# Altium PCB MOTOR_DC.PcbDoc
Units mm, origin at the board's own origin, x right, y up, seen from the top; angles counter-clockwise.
Board outline 21.59 x 21.08 mm, 2 copper layers (Top Layer, Bottom Layer); 7 components, 7 nets, 22 pads, 0 vias.
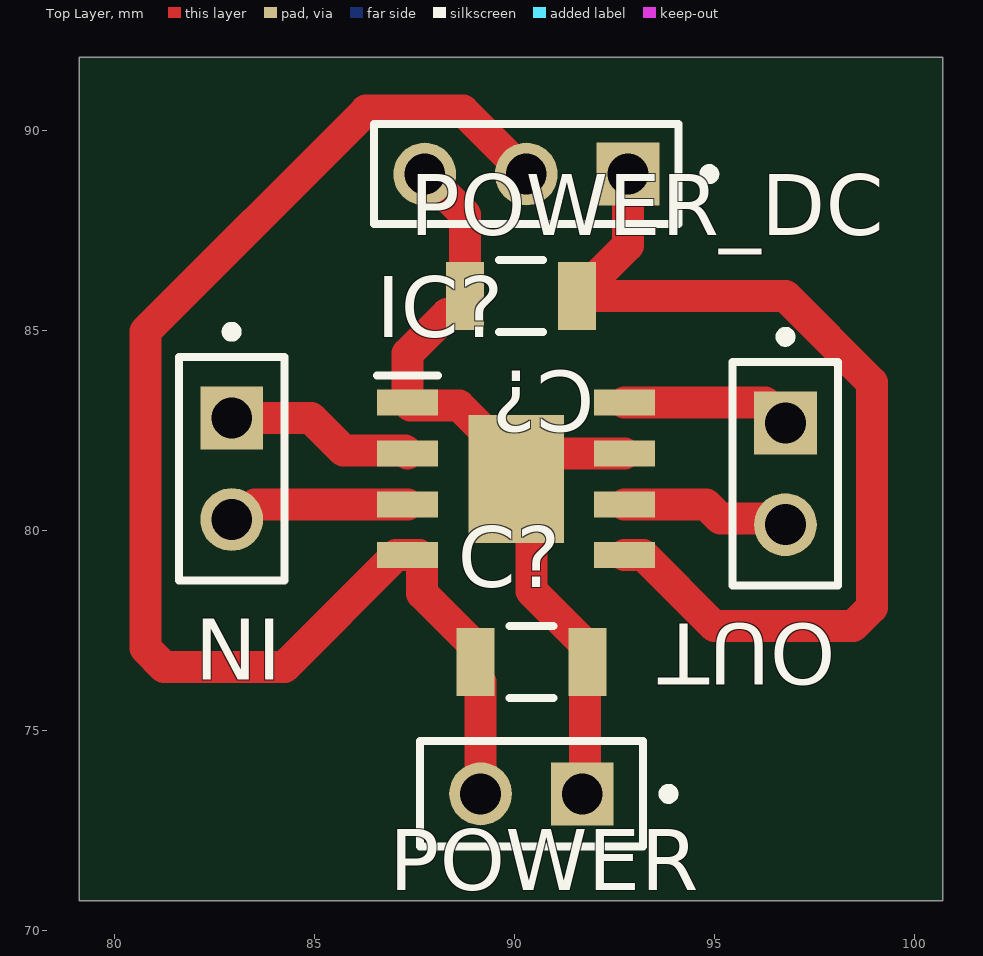
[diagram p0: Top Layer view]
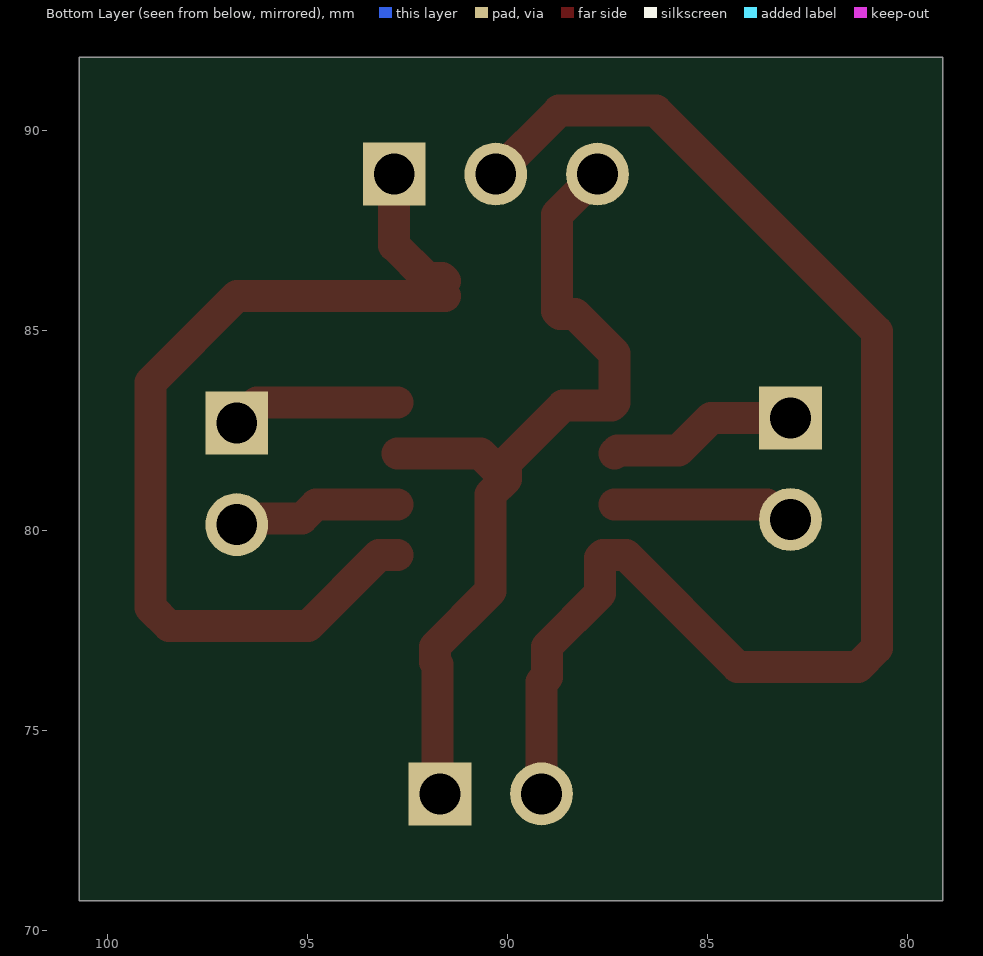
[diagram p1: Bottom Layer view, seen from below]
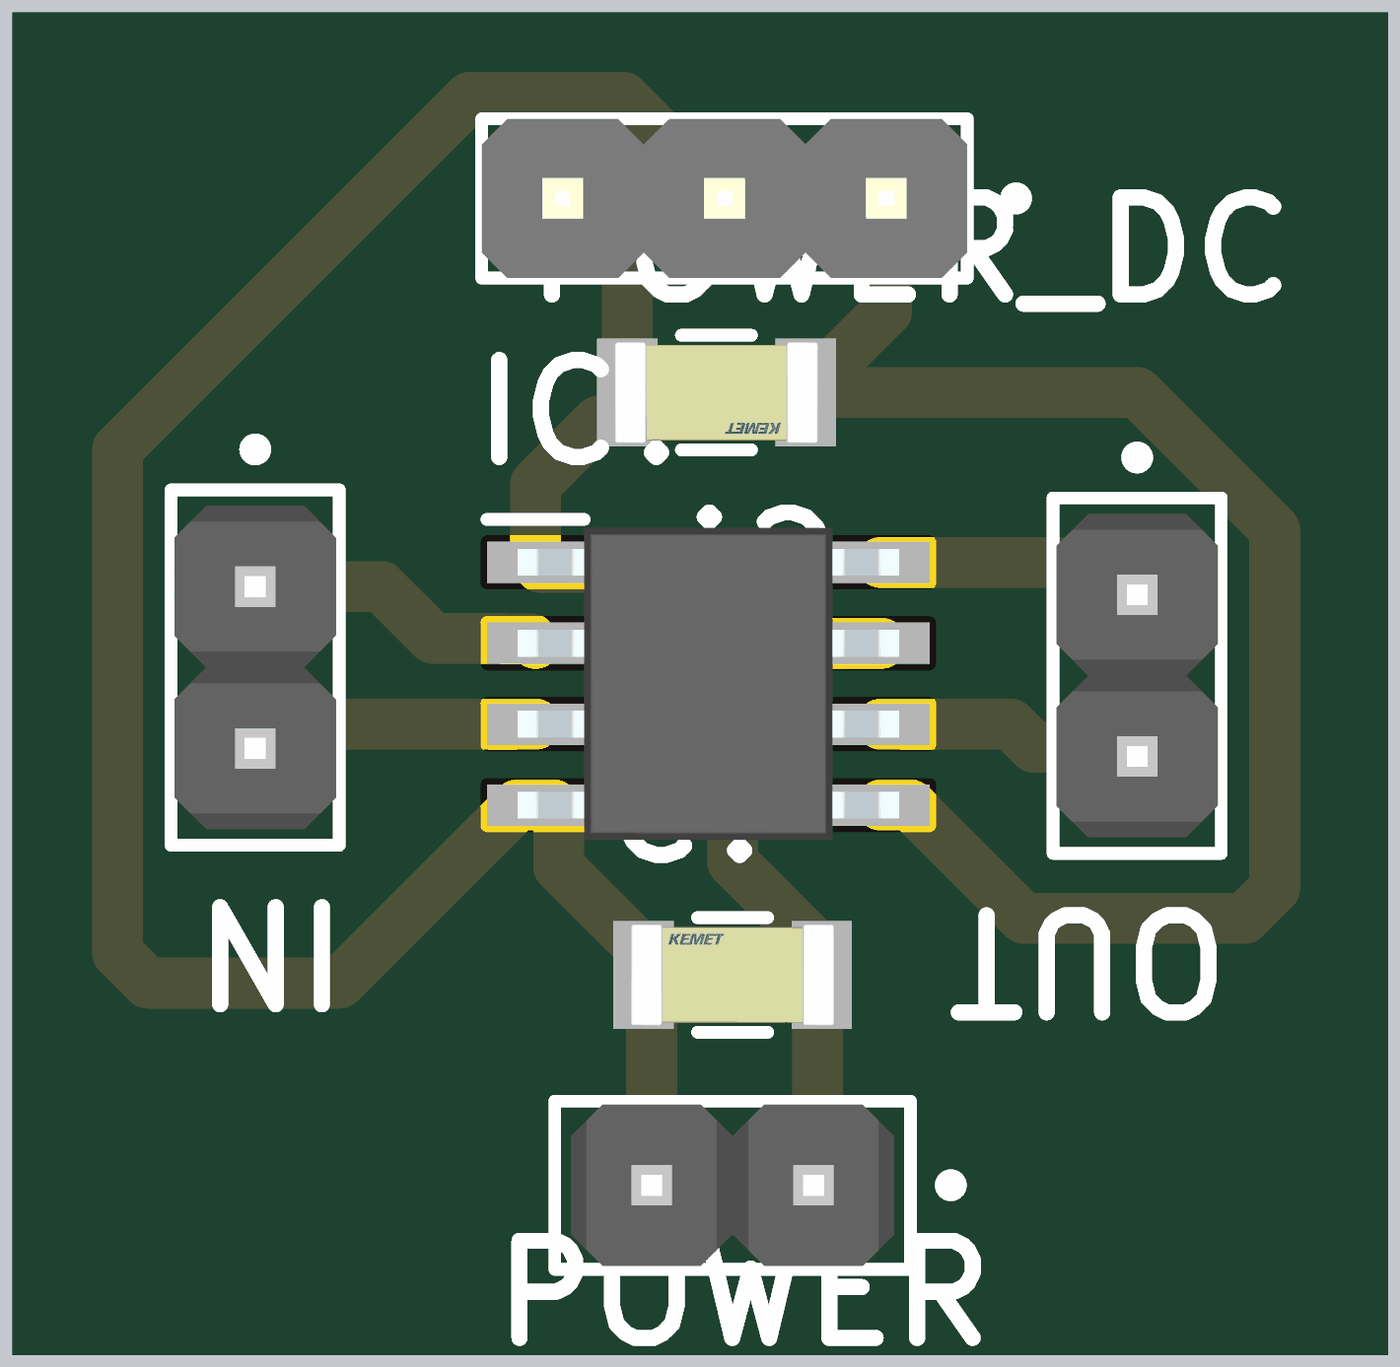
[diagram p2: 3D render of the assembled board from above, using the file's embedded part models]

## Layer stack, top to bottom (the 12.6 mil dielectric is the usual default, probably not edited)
Top Solder: solder mask 0.0102, Solder Resist, Dk 3.5
Top Layer: signal copper 0.0356
Dielectric 1: dielectric 0.32, FR-4, Dk 4.8
Bottom Layer: signal copper 0.0356
Bottom Solder: solder mask 0.0102, Solder Resist, Dk 3.5

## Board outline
79.121,70.739 79.121,91.821 100.711,91.821 100.711,70.739

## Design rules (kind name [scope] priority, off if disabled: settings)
Clearance [All] p1: gap=0.4 ignorepadtopadclearanceinfootprint=FALSE
PolygonConnect [All] p1: connectstyle=Relief reliefconductorwidth=0.254 reliefentries=4 polygonreliefangle="90 Angle" airgapwidth=0.254
RoutingVias [All] p1: holewidth=0.711 width=1.27 viastyle="Through Hole" minholewidth=0.711 minwidth=1.27 maxholewidth=0.711 maxwidth=1.27
SolderMaskExpansion [All] p1: expansion=0.102 istentingtop=FALSE
SupplyNets "Schematic Supply Nets" [InNet('GND')] p1: voltage=0.000
Width [All] p1: maxlimit=0.8 minlimit=0.254 preferedwidth=0.8 toplayer_minwidth=0.8 bottomlayer_maxwidth=0.254 bottomlayer_prefwidth=0.254 minimp=50.000000 maximp=50.000000 favimp=50.000000
30 further rules are at their usual default settings.

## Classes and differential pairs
component class MOTOR_DC: C? IC? IN OUT POWER

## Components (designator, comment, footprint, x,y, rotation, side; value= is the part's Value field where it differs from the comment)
C? "." FP-C1206C-EB-MFG 90.424,76.708 r0 top value="100 pF"
C? "." FP-C1206C-EB-MFG 90.17,85.852 r180 top value="100 pF"
IC? "TB67H451FNG" SOIC127P600X170-9N 90.043,81.28 r0 top
IN "M20-9990246" FP-M20-9990246-MFG 82.931,81.534 r270 top
OUT "M20-9990246" FP-M20-9990246-MFG 96.774,81.407 r270 top
POWER "M20-9990246" FP-M20-9990246-MFG 90.424,73.406 r180 top
POWER_DC "" FP-PR20203VBNN-MFG 90.297,88.9 r180 top

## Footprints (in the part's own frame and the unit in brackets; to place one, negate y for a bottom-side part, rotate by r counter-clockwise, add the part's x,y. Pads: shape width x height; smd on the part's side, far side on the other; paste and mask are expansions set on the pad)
FP-C1206C-EB-MFG [mm]
  rect 0.95x1.7 smd paste+0 mask+0: 1(-1.4,0) 2(1.4,0)
  silkscreen extent -0.55,-0.9 0.55,0.9, body extent -2,-1 2,1, height 0.25
FP-M20-9990246-MFG [mm]
  rect 1.57x1.57 hole 1.02 paste-2539.97 mask+0: 1(-1.27,0)
  round 1.57 hole 1.02 paste-2539.97 mask+0: 2(1.27,0)
  silkscreen extent -3.55,-1.32 2.79,1.32, body extent -2.89,-1.42 2.89,1.42, height 0.25
FP-PR20203VBNN-MFG [mm]
  rect 1.57x1.57 hole 1.02 paste-2539.97 mask+0: 1(-2.54,0)
  round 1.57 hole 1.02 paste-2539.97 mask+0: 2(0,0) 3(2.54,0)
  silkscreen extent -4.7,-1.25 3.81,1.25, body extent -3.81,-1.25 3.81,1.25, height 8.6
SOIC127P600X170-9N [mm]
  rect 1.525x0.65 smd: 1(-2.712,1.905) 2(-2.712,0.635) 3(-2.712,-0.635) 4(-2.712,-1.905) 5(2.712,-1.905) 6(2.712,-0.635) 7(2.712,0.635) 8(2.712,1.905)
  rect 2.39x3.2 smd: 9(0,0)
  silkscreen extent -3.47,2.58 -1.95,2.58, body extent -3,-2.45 3,2.45, height 1.7

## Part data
C? C?: library part CMP-03020-023751-1, "C1206 100 pF X8R 10.00% 50 V", Capacitance="100 pF", Manufacturer=KEMET, Manufacturer Part Number=C1206C101K5HACTU, Package=C1206C-EB, Temperature="-55°C to +150°C", Temperature Characteristic=X8R, Temperature Coefficient=15%, Temperature Range High=+150°C, Temperature Range Low=-55°C, Tolerance=0.1, Voltage Rating="50 V"
IC?: "Integrated Circuit", Manufacturer_Name=Toshiba, Mouser Part Number=N/A
IN OUT POWER: library part CMP-15831-000009-1, "CONN HEADER VERT 2POS 2.54MM", Current Rating=3A, Manufacturer=Harwin, Temperature="-40°C to +105°C", Temperature Range High=+105°C, Temperature Range Low=-40°C
POWER_DC: library part CMP-77940-000002-1, "CONN HEADER VERT 3POS 2.54MM", Current Rating=3A, Manufacturer="Metz Connect", Manufacturer Part Number=PR20203VBNN, Temperature="-40°C to +105°C", Temperature Range High=+105°C, Temperature Range Low=-40°C

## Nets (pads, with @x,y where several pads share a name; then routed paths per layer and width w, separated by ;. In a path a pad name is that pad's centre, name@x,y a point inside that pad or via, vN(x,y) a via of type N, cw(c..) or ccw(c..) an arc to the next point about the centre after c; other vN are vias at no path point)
3V3: C?.1@89.024,76.708 IC?.4 POWER.2 POWER_DC.2 | length 35.2
  Top Layer w0.8: POWER.2 89.154,76.203 89.024,76.333 89.024,76.708 89.024,77.083 87.693,78.414 87.693,79.3 87.618,79.375 IC?.4 87.044,79.375 84.25,76.581 81.241,76.581 80.772,77.05 80.772,84.963 86.294,90.485 88.712,90.485 POWER_DC.2
+5V: C?.1@91.57,85.852 IC?.5 POWER_DC.1 | length 24.4
  Top Layer w0.8: C?.1@91.57,85.852 96.774,85.852 98.933,83.693 98.933,78.066 98.464,77.597 94.996,77.597 93.218,79.375 IC?.5 ; C?.1@91.57,86.227 91.645,86.302 92.02,86.302 92.837,87.119 POWER_DC.1
GND: C?.2 IC?.1 IC?.7 IC?.9 POWER.1 POWER_DC.3 | length 22.3
  Top Layer w0.8: POWER_DC.3 88.77,87.887 88.77,85.852 88.77,85.477 88.695,85.402 88.32,85.402 87.331,84.413 IC?.1 87.406,83.11 88.618,83.11 90.043,81.685 IC?.9 ; POWER.1 91.759,73.471 91.759,76.643 91.824,76.708 91.824,77.083 90.427,78.48 90.427,80.896 IC?.9 ; IC?.7 90.678,81.915 IC?.9
IN1: IC?.3 IN.2 | length 4.6
  Top Layer w0.8: IN.2 83.139,80.264 83.52,80.645 IC?.3
IN2: IC?.2 IN.1 | length 4.8
  Top Layer w0.8: IN.1 84.916,82.804 85.73,81.99 86.829,81.99 86.834,81.985 87.261,81.985 IC?.2
OUT1: IC?.6 OUT.2 | length 4.2
  Top Layer w0.8: IC?.6 94.788,80.645 95.149,80.284 96.627,80.284 OUT.2
OUT2: IC?.8 OUT.1 | length 4.2
  Top Layer w0.8: IC?.8 96.266,83.185 OUT.1

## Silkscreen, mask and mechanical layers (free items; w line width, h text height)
Mechanical 1:
  the board outline again, w1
